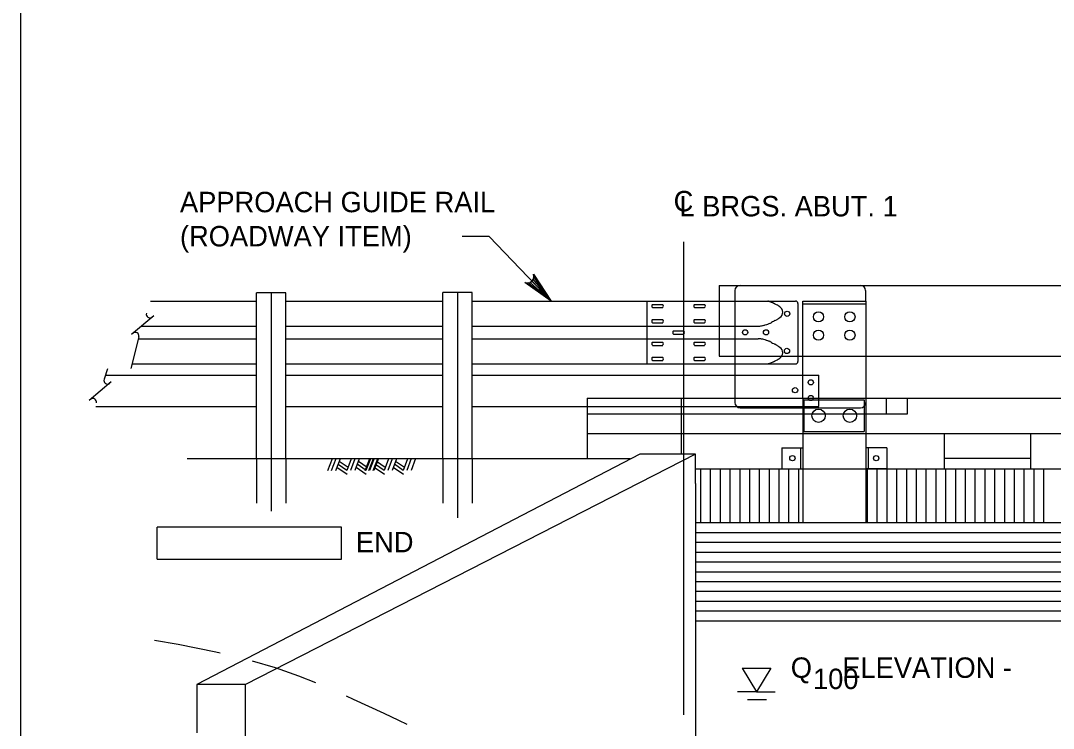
# Model space of a CAD drawing. Extents: x 638263 to 640360, y 293683 to 298655.
# Drawn here: x 638475.5 to 638627.4, y 296853.1 to 296957.1 of the extents above; entities that cross this region are included whole.
import ezdxf

# ---------------------------------------------------------------- set-up
doc = ezdxf.new("R2010")
doc.units = 0
for name, color, linetype in [('2', 7, 'Continuous'), ('3', 7, 'Continuous'), ('4', 7, 'Continuous'), ('5', 7, 'Continuous'), ('8', 7, 'Continuous'), ('Level 25', 7, 'Continuous')]:
    doc.layers.add(name, color=color, linetype=linetype)

msp = doc.modelspace()

# ---------------------------------------------------------------- linework, layer by layer
at = {"layer": '2'}
for p, q in [((638475.46, 296668.46), (638475.46, 297232.46)), ((638578.19, 296918.22), (638578.19, 296915.91)), ((638578.19, 296918.22), (638751.85, 296918.22)), ((638494.57, 296915.92), (638510.14, 296915.92)), ((638514.47, 296915.92), (638537.53, 296915.92)), ((638541.86, 296915.92), (638567.54, 296915.92)), ((638567.54, 296915.92), (638567.54, 296906.68)), ((638567.61, 296915.92), (638578.19, 296915.92)), ((638578.19, 296915.92), (638589.41, 296915.92)), ((638578.19, 296915.9), (638578.19, 296907.82)), ((638590.51, 296915.9), (638599.75, 296915.9)), ((638590.51, 296901.66), (638590.51, 296915.9)), ((638599.75, 296915.9), (638599.75, 296901.66)), ((638568.41, 296915.41), (638569.89, 296915.41)), ((638568.41, 296914.95), (638569.89, 296914.95)), ((638574.58, 296915.41), (638576.06, 296915.41)), ((638574.58, 296914.95), (638576.06, 296914.95)), ((638589.78, 296915.55), (638589.78, 296907.05)), ((638590.51, 296915.52), (638599.75, 296915.52)), ((638568.41, 296913.19), (638569.89, 296913.19)), ((638574.58, 296913.19), (638576.06, 296913.19)), ((638493.21, 296912.22), (638510.14, 296912.22)), ((638514.47, 296912.22), (638537.53, 296912.22)), ((638541.86, 296912.22), (638578.19, 296912.22)), ((638568.41, 296912.73), (638569.89, 296912.73)), ((638571.49, 296911.53), (638572.97, 296911.53)), ((638574.58, 296912.73), (638576.06, 296912.73)), ((638578.19, 296912.22), (638583.94, 296912.22)), ((638492.77, 296910.37), (638510.14, 296910.37)), ((638514.47, 296910.37), (638537.53, 296910.37)), ((638541.86, 296910.37), (638578.19, 296910.37)), ((638568.41, 296909.87), (638569.89, 296909.87)), ((638571.49, 296911.07), (638572.97, 296911.07)), ((638574.58, 296909.87), (638576.06, 296909.87)), ((638578.19, 296910.37), (638583.94, 296910.37)), ((638568.41, 296909.4), (638569.89, 296909.4)), ((638574.58, 296909.4), (638576.06, 296909.4)), ((638568.41, 296907.65), (638569.89, 296907.65)), ((638568.41, 296907.19), (638569.89, 296907.19)), ((638574.58, 296907.65), (638576.06, 296907.65)), ((638574.58, 296907.19), (638576.06, 296907.19)), ((638578.19, 296907.82), (638580.5, 296907.82)), ((638580.5, 296907.82), (638590.51, 296907.82)), ((638590.51, 296907.82), (638599.75, 296907.82)), ((638599.75, 296907.82), (638636.81, 296907.82)), ((638491.85, 296906.68), (638510.14, 296906.68)), ((638514.47, 296906.68), (638537.53, 296906.68)), ((638541.86, 296906.68), (638580.5, 296906.68)), ((638580.5, 296906.68), (638589.41, 296906.68)), ((638487.91, 296905.02), (638510.14, 296905.02)), ((638514.47, 296905.02), (638537.53, 296905.02)), ((638541.86, 296905.02), (638580.5, 296905.02)), ((638580.5, 296905.02), (638592.86, 296905.02)), ((638592.86, 296900.4), (638592.86, 296905.02)), ((638558.76, 296901.66), (638590.51, 296901.66)), ((638558.76, 296901.66), (638558.76, 296892.71)), ((638572.61, 296901.66), (638572.61, 296893.43)), ((638590.51, 296901.66), (638599.75, 296901.66)), ((638590.51, 296901.66), (638590.51, 296883.34)), ((638590.67, 296901.38), (638590.67, 296896.76)), ((638590.67, 296901.38), (638599.55, 296901.38)), ((638599.55, 296901.38), (638599.55, 296896.76)), ((638599.75, 296901.66), (638599.75, 296883.34)), ((638599.75, 296901.66), (638636.81, 296901.66)), ((638602.82, 296899.35), (638602.82, 296901.66)), ((638605.92, 296899.35), (638605.92, 296901.66)), ((638486.52, 296900.4), (638510.14, 296900.4)), ((638514.47, 296900.4), (638537.53, 296900.4)), ((638541.86, 296900.4), (638558.76, 296900.4)), ((638558.76, 296900.4), (638592.86, 296900.4)), ((638558.76, 296899.35), (638605.92, 296899.35)), ((638558.76, 296896.46), (638590.51, 296896.46)), ((638590.51, 296896.46), (638599.75, 296896.46)), ((638590.67, 296896.76), (638599.55, 296896.76)), ((638599.75, 296896.46), (638615.9, 296896.46)), ((638611.28, 296896.46), (638611.28, 296891.27)), ((638611.5, 296896.46), (638636.81, 296896.46)), ((638624, 296896.46), (638624, 296891.27)), ((638587.42, 296894.36), (638590.51, 296894.36)), ((638587.42, 296894.36), (638587.42, 296891.27)), ((638590.15, 296894.36), (638590.15, 296891.27)), ((638590.51, 296894.36), (638590.51, 296891.27)), ((638602.84, 296894.36), (638599.75, 296894.36)), ((638599.75, 296894.36), (638599.75, 296891.27)), ((638600.11, 296894.36), (638600.11, 296891.27)), ((638602.84, 296894.36), (638602.84, 296891.27)), ((638611.28, 296892.8), (638624, 296892.8)), ((638587.42, 296891.27), (638590.51, 296891.27)), ((638590.51, 296891.27), (638599.75, 296891.27)), ((638602.84, 296891.27), (638599.75, 296891.27))]:
    msp.add_line(p, q, dxfattribs=at)
for centre, radius in [((638588.2, 296914.04), 0.385), ((638592.82, 296913.59), 0.748), ((638597.43, 296913.59), 0.748), ((638582.01, 296911.31), 0.385), ((638585.09, 296911.31), 0.385), ((638592.82, 296910.9), 0.748), ((638597.43, 296910.9), 0.748), ((638588.17, 296908.58), 0.385), ((638591.67, 296903.96), 0.385), ((638589.36, 296902.81), 0.385), ((638591.67, 296901.66), 0.385), ((638592.82, 296899.06), 0.978), ((638597.43, 296899.06), 0.978), ((638588.97, 296892.82), 0.385), ((638601.29, 296892.82), 0.385)]:
    msp.add_circle(centre, radius, dxfattribs=at)
for centre, radius, start, end in [((638582.37, 296906.19), 10.17, 71.5066, 72.9766), ((638589.41, 296915.55), 0.369, 0, 90), ((638568.55, 296915.18), 0.269, 120.8559, 239.1441), ((638569.75, 296915.18), 0.269, 300.8559, 59.1441), ((638574.72, 296915.18), 0.269, 120.8559, 239.1441), ((638575.92, 296915.18), 0.269, 300.8559, 59.1441), ((638585, 296914.05), 1.88, 68.0907, 71.5066), ((638561.55, 296855.75), 64.73, 67.6851, 68.0907), ((638583.87, 296910.14), 5.93, 66.3453, 67.6851), ((638585.28, 296913.36), 2.42, 63.4251, 66.3453), ((638572.13, 296887.08), 31.8, 62.6202, 63.4251), ((638586.32, 296914.47), 0.955, 54.6771, 62.6202), ((638584.32, 296911.64), 4.42, 50.9849, 54.6771), ((638586.64, 296914.29), 0.916, 301.3851, 59.6468), ((638568.55, 296912.96), 0.269, 120.8559, 239.1441), ((638569.75, 296912.96), 0.269, 300.8559, 59.1441), ((638574.72, 296912.96), 0.269, 120.8559, 239.1441), ((638575.92, 296912.96), 0.269, 300.8559, 59.1441), ((638641.25, 296811.86), 115.08, 118.565, 118.7501), ((638646.64, 296801.96), 126.36, 118.4725, 118.565), ((638399.12, 297258.35), 392.83, 298.4725, 298.525), ((638586.2, 296914.16), 1.09, 298.525, 306.8818), ((638583.89, 296917.24), 4.94, 306.8818, 310.7993), ((638571.63, 296911.3), 0.269, 120.8559, 239.1441), ((638572.83, 296911.3), 0.269, 300.8559, 59.1441), ((638583.71, 296917.25), 5.03, 272.6429, 278.367), ((638584.13, 296914.41), 2.16, 278.367, 287.1115), ((638557.71, 297000.23), 91.96, 287.1115, 287.3611), ((638584.21, 296915.46), 3.14, 287.3611, 288.7111), ((638579.39, 296929.7), 18.18, 288.7111, 290.2329), ((638585.45, 296913.25), 0.644, 290.2329, 298.3215), ((638575.58, 296931.57), 21.45, 298.3215, 298.7501), ((638568.55, 296909.64), 0.269, 120.8559, 239.1441), ((638569.75, 296909.64), 0.269, 300.8559, 59.1441), ((638574.72, 296909.64), 0.269, 120.8559, 239.1441), ((638575.92, 296909.64), 0.269, 300.8559, 59.1441), ((638583.71, 296905.35), 5.03, 81.633, 87.3571), ((638584.13, 296908.19), 2.16, 72.8885, 81.633), ((638557.71, 296822.36), 91.96, 72.6389, 72.8885), ((638584.21, 296907.13), 3.14, 71.2889, 72.6389), ((638579.39, 296892.9), 18.18, 69.7671, 71.2889), ((638585.45, 296909.35), 0.644, 61.6785, 69.7671), ((638575.58, 296891.03), 21.45, 61.2499, 61.6785), ((638641.25, 297010.73), 115.08, 241.2499, 241.435), ((638646.64, 297020.64), 126.36, 241.435, 241.5275), ((638399.12, 296564.24), 392.83, 61.475, 61.5275), ((638586.2, 296908.43), 1.09, 53.1182, 61.475), ((638583.89, 296905.35), 4.94, 49.2007, 53.1182), ((638586.64, 296908.31), 0.916, 300.3532, 58.6149), ((638568.55, 296907.42), 0.269, 120.8559, 239.1441), ((638569.75, 296907.42), 0.269, 300.8559, 59.1441), ((638574.72, 296907.42), 0.269, 120.8559, 239.1441), ((638575.92, 296907.42), 0.269, 300.8559, 59.1441), ((638582.37, 296916.4), 10.17, 287.0234, 288.4934), ((638585, 296908.55), 1.88, 288.4934, 291.9093), ((638561.55, 296966.85), 64.73, 291.9093, 292.3149), ((638583.87, 296912.46), 5.93, 292.3149, 293.6547), ((638585.28, 296909.24), 2.42, 293.6547, 296.5749), ((638572.13, 296935.52), 31.8, 296.5749, 297.3798), ((638586.32, 296908.13), 0.955, 297.3798, 305.3229), ((638584.32, 296910.95), 4.42, 305.3229, 309.0151), ((638589.41, 296907.05), 0.369, 270, 0)]:
    msp.add_arc(centre, radius, start, end, dxfattribs=at)
at = {"layer": '3'}
for p, q in [((638514.47, 296917.1), (638510.14, 296917.1)), ((638510.14, 296892.71), (638510.14, 296917.1)), ((638512.3, 296917.1), (638512.3, 296885.02)), ((638514.47, 296892.71), (638514.47, 296917.1)), ((638537.53, 296892.71), (638537.53, 296917.18)), ((638541.86, 296917.18), (638537.53, 296917.18)), ((638539.7, 296917.18), (638539.7, 296884.06)), ((638541.86, 296892.71), (638541.86, 296917.18)), ((638495.03, 296913.74), (638491.76, 296911)), ((638492.84, 296910.66), (638491.67, 296905.99)), ((638488.22, 296905.96), (638487.72, 296904.41)), ((638488.79, 296904.02), (638485.52, 296901.28)), ((638566.52, 296893.43), (638501.39, 296859.55)), ((638574.73, 296893.43), (638508.52, 296859.55)), ((638574.73, 296893.43), (638566.52, 296893.43)), ((638574.73, 296889.11), (638574.73, 296893.43)), ((638565.13, 296892.71), (638499.94, 296892.71)), ((638510.14, 296892.71), (638510.14, 296886.22)), ((638514.47, 296892.71), (638514.47, 296886.22)), ((638521.27, 296892.71), (638520.6, 296890.96)), ((638521.81, 296892.72), (638521.15, 296890.96)), ((638522.45, 296892.73), (638521.78, 296890.97)), ((638522.16, 296891.96), (638523.45, 296891.06)), ((638522.32, 296892.39), (638523.61, 296891.49)), ((638524.08, 296892.73), (638523.42, 296891)), ((638524.63, 296892.73), (638523.97, 296891.01)), ((638525.26, 296892.74), (638524.61, 296891.02)), ((638524.97, 296891.97), (638526.26, 296891.07)), ((638525.13, 296892.4), (638526.42, 296891.5)), ((638526.75, 296892.71), (638526.08, 296890.96)), ((638526.89, 296892.74), (638526.23, 296891.01)), ((638527.29, 296892.72), (638526.63, 296890.96)), ((638527.43, 296892.75), (638526.78, 296891.02)), ((638527.93, 296892.73), (638527.26, 296890.97)), ((638528.07, 296892.75), (638527.42, 296891.03)), ((638527.63, 296891.96), (638528.92, 296891.06)), ((638527.8, 296892.39), (638529.09, 296891.49)), ((638529.56, 296892.73), (638528.9, 296891)), ((638530.11, 296892.73), (638529.45, 296891.01)), ((638530.74, 296892.74), (638530.09, 296891.02)), ((638530.45, 296891.97), (638531.73, 296891.07)), ((638530.61, 296892.4), (638531.9, 296891.5)), ((638532.37, 296892.74), (638531.71, 296891.01)), ((638532.91, 296892.75), (638532.26, 296891.02)), ((638533.55, 296892.75), (638532.9, 296891.03)), ((638537.53, 296892.71), (638537.53, 296886.22)), ((638541.86, 296892.71), (638541.86, 296886.22)), ((638521.98, 296891.51), (638523.48, 296890.47)), ((638524.8, 296891.52), (638526.3, 296890.48)), ((638527.46, 296891.51), (638528.96, 296890.47)), ((638530.27, 296891.52), (638531.77, 296890.48)), ((638574.73, 296891.27), (638590.51, 296891.27)), ((638599.75, 296891.27), (638636.81, 296891.27)), ((638574.73, 296889.11), (638574.73, 296826.38)), ((638574.73, 296883.34), (638753.51, 296883.34)), ((638574.73, 296868.92), (638753.51, 296868.92)), ((638508.52, 296859.55), (638501.39, 296859.55)), ((638501.39, 296859.55), (638501.39, 296852.43)), ((638508.52, 296851.68), (638508.52, 296859.55))]:
    msp.add_line(p, q, dxfattribs=at)
for centre, start, end in [((638494.47, 296913.97), 162.1496, 312.1496), ((638492.32, 296910.78), 347.4782, 130.0168), ((638492.32, 296910.78), 130.0028, 130.0168), ((638488.23, 296904.25), 162.1496, 312.1496), ((638486.08, 296901.06), 347.4782, 130.0168)]:
    msp.add_arc(centre, 0.533, start, end, dxfattribs=at)
at = {"layer": '4'}
for p, q in [((638544.36, 296925.38), (638540.41, 296925.38)), ((638553.49, 296915.92), (638544.36, 296925.38)), ((638572.93, 296924.61), (638572.93, 296855.1)), ((638522.67, 296882.7), (638495.52, 296882.7)), ((638495.52, 296877.99), (638495.52, 296882.7)), ((638522.67, 296877.99), (638522.67, 296882.7)), ((638495.52, 296877.99), (638522.67, 296877.99)), ((638581.56, 296861.97), (638583.68, 296858.48)), ((638581.56, 296861.97), (638585.8, 296861.97)), ((638585.8, 296861.97), (638583.68, 296858.48)), ((638583.68, 296858.48), (638580.91, 296858.48)), ((638583.68, 296858.48), (638586.45, 296858.48)), ((638582.37, 296857.34), (638585.14, 296857.34))]:
    msp.add_line(p, q, dxfattribs=at)
msp.add_lwpolyline([(638553.49, 296915.92), (638549.62, 296918.66), (638550.05, 296918.58), (638550.41, 296918.66), (638550.67, 296918.84), (638550.86, 296919.1), (638550.95, 296919.45), (638550.88, 296919.88), (638553.49, 296915.92), (638550.95, 296919.45), (638550.86, 296919.1), (638553.49, 296915.92), (638550.67, 296918.84), (638550.41, 296918.66), (638553.49, 296915.92), (638550.05, 296918.58)], dxfattribs=at)
at = {"layer": '5'}
for p, q in [((638575.45, 296891.27), (638575.45, 296883.34)), ((638576.89, 296891.27), (638576.89, 296883.34)), ((638578.33, 296891.27), (638578.33, 296883.34)), ((638579.77, 296891.27), (638579.77, 296883.34)), ((638581.22, 296891.27), (638581.22, 296883.34)), ((638582.66, 296891.27), (638582.66, 296883.34)), ((638584.1, 296891.27), (638584.1, 296883.34)), ((638585.54, 296891.27), (638585.54, 296883.34)), ((638586.98, 296891.27), (638586.98, 296883.34)), ((638588.42, 296891.27), (638588.42, 296883.34)), ((638589.87, 296891.27), (638589.87, 296883.34)), ((638599.96, 296891.27), (638599.96, 296883.34)), ((638601.4, 296891.27), (638601.4, 296883.34)), ((638602.84, 296891.27), (638602.84, 296883.34)), ((638604.29, 296891.27), (638604.29, 296883.34)), ((638605.73, 296891.27), (638605.73, 296883.34)), ((638607.17, 296891.27), (638607.17, 296883.34)), ((638608.61, 296891.27), (638608.61, 296883.34)), ((638610.05, 296891.27), (638610.05, 296883.34)), ((638611.49, 296891.27), (638611.49, 296883.34)), ((638612.94, 296891.27), (638612.94, 296883.34)), ((638614.38, 296891.27), (638614.38, 296883.34)), ((638615.82, 296891.27), (638615.82, 296883.34)), ((638617.26, 296891.27), (638617.26, 296883.34)), ((638618.7, 296891.27), (638618.7, 296883.34)), ((638620.15, 296891.27), (638620.15, 296883.34)), ((638621.59, 296891.27), (638621.59, 296883.34)), ((638623.03, 296891.27), (638623.03, 296883.34)), ((638624.47, 296891.27), (638624.47, 296883.34)), ((638625.91, 296891.27), (638625.91, 296883.34)), ((638574.73, 296881.9), (638753.51, 296881.9)), ((638574.73, 296880.46), (638753.51, 296880.46)), ((638574.73, 296879.01), (638753.51, 296879.01)), ((638574.73, 296877.57), (638753.51, 296877.57)), ((638574.73, 296876.13), (638753.51, 296876.13)), ((638574.73, 296874.69), (638753.51, 296874.69)), ((638574.73, 296873.25), (638753.51, 296873.25)), ((638574.73, 296871.81), (638753.51, 296871.81)), ((638574.73, 296870.36), (638753.51, 296870.36))]:
    msp.add_line(p, q, dxfattribs=at)
at = {"layer": '8'}
for p, q in [((638498.6, 296865.43), (638495.13, 296866)), ((638504.18, 296864.31), (638498.6, 296865.43)), ((638504.8, 296864.16), (638504.18, 296864.31)), ((638512.96, 296861.98), (638509.57, 296862.97)), ((638516.39, 296860.79), (638512.96, 296861.98)), ((638518.88, 296859.81), (638516.39, 296860.79)), ((638524.39, 296857.36), (638523.39, 296857.82)), ((638526.69, 296856.3), (638524.39, 296857.36)), ((638528.91, 296855.28), (638526.69, 296856.3)), ((638531.06, 296854.26), (638528.91, 296855.28)), ((638532.31, 296853.66), (638531.06, 296854.26))]:
    msp.add_line(p, q, dxfattribs=at)
at = {"layer": 'Level 25'}
for p, q in [((638580.5, 296917.45), (638580.5, 296915.91)), ((638581.27, 296918.22), (638598.97, 296918.22)), ((638599.74, 296917.45), (638599.74, 296915.9)), ((638580.5, 296915.91), (638580.5, 296906.67)), ((638580.5, 296906.67), (638580.5, 296901.66)), ((638580.5, 296901.66), (638580.5, 296901)), ((638581.27, 296900.23), (638598.97, 296900.23))]:
    msp.add_line(p, q, dxfattribs=at)
for centre, start, end in [((638581.27, 296917.45), 90, 180), ((638598.97, 296917.45), 0, 90), ((638581.27, 296901), 180, 270), ((638598.97, 296901), 270, 0)]:
    msp.add_arc(centre, 0.77, start, end, dxfattribs=at)

# ---------------------------------------------------------------- texts
at = {"layer": '4'}
for s, p in [('APPROACH GUIDE RAIL', (638498.89, 296928.97)), ('C', (638571.5, 296929.1)), ('L BRGS. ABUT. 1', (638572.36, 296928.36)), ('(ROADWAY ITEM)', (638498.89, 296923.95)), ('END', (638524.77, 296878.98)), ('Q    ELEVATION - ', (638588.73, 296860.53)), ('100', (638592, 296858.88))]:
    msp.add_text(s, height=3, dxfattribs=at).set_placement(p)

doc.saveas('drawing.dxf')
